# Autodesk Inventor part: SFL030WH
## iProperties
Created: 2005-10
Part Number: SFL030WH
Material: 1.4301 X5CrNi10-10 A2
Document SubType Name: Modellieren
Designer: Mittelmeyer
Manufacturer: Standard
Standards Organization: Custom
Description: Drehdurchführung mit Flansch d=30mm
Author: Mittelmeyer
Comments: Ferrofluidics
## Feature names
1. Extrusion2
2. Extrusion3
3. Extrusion4
4. Extrusion5
5. Extrusion6
6. Rundung3 [Fillet]
7. Fase1 [Chamfer]
8. Fase2 [Chamfer]
9. Bohrung1 [Hole]
10. Runde Anordnung1 [Circular Pattern]
